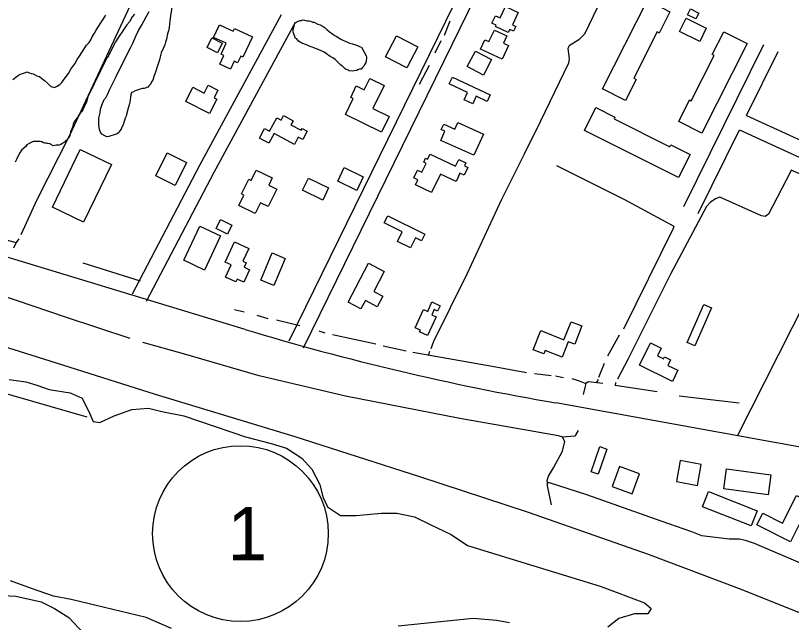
# Model space of a CAD drawing. Extents: x 3361039 to 3398939, y 576572 to 602007.
# Drawn here: x 3384364 to 3385821, y 582965 to 584104 of the extents above; entities that cross this region are included whole.
import ezdxf

# ---------------------------------------------------------------- set-up
doc = ezdxf.new("R2010")
doc.units = 0
for name, color, linetype in [('V-BLDG-OTLN', 7, 'Continuous'), ('V-RAIL-TRAK', 7, 'Continuous'), ('V-ROAD-CNTR', 7, 'Continuous'), ('V-ROAD-IDEN', 7, 'Continuous'), ('V-SITE-VEGE', 7, 'Continuous'), ('V-TOPO-SHOR', 7, 'Continuous')]:
    doc.layers.add(name, color=color, linetype=linetype)

msp = doc.modelspace()

# ---------------------------------------------------------------- linework, layer by layer
at = {"layer": 'V-BLDG-OTLN'}
for points in [[(3385466.3, 583966.4), (3385550.7, 584132.7), (3385592.8, 584111.3), (3385572.4, 584071.3), (3385568.6, 584073.2), (3385524.7, 583986.7), (3385529.4, 583984.3), (3385509.3, 583944.6)], [(3385289, 584072.2), (3385265, 584083.5), (3385266.2, 584085.9), (3385258.3, 584089.6), (3385265, 584103.8), (3385274, 584099.6), (3385284, 584120.9), (3385307.9, 584109.7), (3385296.9, 584086.5), (3385303.1, 584083.5), (3385299, 584074.6), (3385291.8, 584078)], [(3385641.2, 584097.8), (3385625.6, 584105.7), (3385631.2, 584116.6), (3385646.8, 584108.7)], [(3385648.8, 584055.6), (3385611, 584074.1), (3385623.3, 584099.2), (3385661.1, 584080.6)], [(3384746.7, 584086.7), (3384772.5, 584074.7), (3384775, 584080), (3384808.8, 584064.2), (3384791, 584026), (3384786.8, 584028), (3384780.8, 584015.3), (3384774.3, 584018.3), (3384767.3, 584003.3), (3384747.3, 584012.6), (3384755, 584029.2), (3384749.9, 584031.6), (3384759.4, 584052), (3384735.6, 584063.1)], [(3385119.2, 584045.3), (3385098.8, 584005.9), (3385058.9, 584026.6), (3385079.3, 584066)], [(3385277.5, 584021.9), (3385237.1, 584040.9), (3385245.3, 584058.6), (3385252.8, 584055.1), (3385263, 584076.9), (3385286.5, 584065.9), (3385280, 584052.1), (3385289.6, 584047.6)], [(3385737.9, 584051.4), (3385652.5, 583883.5), (3385609.3, 583905.5), (3385629.7, 583945.7), (3385632.4, 583944.3), (3385675.6, 584029.1), (3385672.2, 584030.8), (3385694, 584073.7)], [(3384732.5, 584062), (3384752.2, 584052.5), (3384743.4, 584034.4), (3384723.7, 584043.9)], [(3385242.5, 583992.3), (3385212, 584008.3), (3385227.4, 584037.5), (3385257.8, 584021.5)], [(3385050.8, 583885.4), (3384983.5, 583918.6), (3384998, 583948.1), (3384993.3, 583950.5), (3385003.8, 583971.9), (3385018.6, 583964.6), (3385029.1, 583986), (3385056.3, 583972.6), (3385035, 583929.5), (3385065.2, 583914.6)], [(3385184.2, 583988.4), (3385255.1, 583955.6), (3385249.3, 583943), (3385228.9, 583952.5), (3385222.4, 583938.5), (3385206.1, 583946.1), (3385212.5, 583959.8), (3385178.3, 583975.7)], [(3384727.9, 583920.1), (3384683.5, 583943), (3384697.1, 583969.4), (3384717.9, 583958.7), (3384725.5, 583973.4), (3384743.9, 583964), (3384736.6, 583949.9), (3384741.9, 583947.2)], [(3385608.8, 583799.9), (3385432.1, 583888.3), (3385453.7, 583931.4), (3385489.4, 583913.5), (3385487.8, 583910.4), (3385592.4, 583858), (3385594.2, 583861.7), (3385630.6, 583843.5)], [(3384887.5, 583862.1), (3384849.5, 583882.5), (3384839.8, 583864.5), (3384821.9, 583874.2), (3384831.5, 583892.1), (3384840.9, 583887.1), (3384854.4, 583912.2), (3384862.5, 583907.9), (3384867.1, 583916.5), (3384885, 583906.8), (3384880.8, 583899.1), (3384900.2, 583888.7), (3384902, 583892), (3384911.4, 583887), (3384903.1, 583871.5), (3384894.8, 583875.9)], [(3385224.5, 583841.8), (3385162.5, 583869.9), (3385170.3, 583887.1), (3385163.3, 583890.3), (3385167.9, 583900.3), (3385189, 583890.7), (3385194.7, 583903.1), (3385242.5, 583881.4)], [(3384433.3, 583744.5), (3384485.5, 583852.7), (3384544, 583824.5), (3384491.8, 583716.3)], [(3384627.5, 583803.2), (3384648.6, 583846.2), (3384685.1, 583828.3), (3384663.9, 583785.3)], [(3385142.2, 583844.2), (3385190.2, 583821.2), (3385196.3, 583834), (3385209.7, 583827.6), (3385207, 583822), (3385213.2, 583819.1), (3385206.3, 583804.7), (3385198.5, 583808.4), (3385191.1, 583792.8), (3385161.9, 583806.7), (3385145.2, 583771.8), (3385114.8, 583786.4), (3385119.4, 583796.1), (3385111.6, 583799.8), (3385118.5, 583814.2), (3385127, 583810.2), (3385134.9, 583826.6), (3385130.4, 583828.7), (3385134, 583836.3), (3385137.6, 583834.5)], [(3384981, 583818.7), (3385016.8, 583801.6), (3385004.6, 583776.1), (3384968.8, 583793.3)], [(3384854.5, 583778.6), (3384838.5, 583745.7), (3384823.8, 583752.8), (3384814, 583732.7), (3384783.4, 583747.6), (3384792.8, 583767), (3384788.2, 583769.3), (3384801.7, 583797), (3384806.3, 583794.8), (3384815.6, 583814), (3384845.8, 583799.3), (3384839.3, 583786)], [(3384914, 583798.7), (3384951.6, 583780.5), (3384940.7, 583757.9), (3384903, 583776.2)], [(3384761.9, 583694.1), (3384740.4, 583704.6), (3384748.6, 583721.2), (3384770.1, 583710.6)], [(3385062.7, 583728.3), (3385132.2, 583694), (3385126, 583681.5), (3385114.9, 583687), (3385105.6, 583668), (3385081.1, 583680.1), (3385090, 583698.2), (3385056.1, 583715)], [(3384748.9, 583690.6), (3384718.6, 583626.4), (3384679.6, 583644.9), (3384709.9, 583709)], [(3384792.5, 583603.6), (3384780, 583609.5), (3384777.6, 583604.2), (3384758.2, 583613.3), (3384768.9, 583636.2), (3384757.3, 583641.6), (3384775, 583679.6), (3384802.2, 583666.9), (3384791, 583642.9), (3384796.9, 583640.1), (3384793.1, 583632), (3384803.5, 583627.2)], [(3384824.2, 583607.7), (3384845.8, 583658.6), (3384870.4, 583648.2), (3384848.8, 583597.3)], [(3384988.2, 583566.3), (3385026.8, 583639.4), (3385056.3, 583623.8), (3385036.7, 583586.5), (3385053.4, 583577.7), (3385042.9, 583557.8), (3385020.8, 583569.5), (3385012.4, 583553.5)], [(3385114.3, 583518.4), (3385129.9, 583552.6), (3385137.8, 583549), (3385145.9, 583566.6), (3385161, 583559.7), (3385156.2, 583549.3), (3385149.8, 583552.3), (3385145.4, 583542.7), (3385153.5, 583539), (3385137.4, 583503.8), (3385122.5, 583510.5), (3385124.1, 583513.9)], [(3385624.9, 583490.6), (3385656.1, 583562.2), (3385670.9, 583555.7), (3385639.7, 583484.1)], [(3385350.1, 583513.1), (3385393.8, 583495.8), (3385407.2, 583529.6), (3385427.5, 583521.6), (3385413.9, 583487.3), (3385401.8, 583492.1), (3385390.4, 583463.2), (3385358.4, 583475.9), (3385355.7, 583469.1), (3385335.8, 583477)], [(3385597.3, 583417.6), (3385535.8, 583447.8), (3385556.3, 583489.7), (3385576.2, 583479.9), (3385569.3, 583465.8), (3385580.9, 583460.1), (3385582.6, 583463.6), (3385593.9, 583458.1), (3385588.7, 583447.6), (3385607.5, 583438.4)], [(3385474.4, 583290.5), (3385457.8, 583243.4), (3385444.6, 583248.1), (3385461.2, 583295.2)], [(3385651.4, 583261.8), (3385612.1, 583268.9), (3385604.9, 583229.6), (3385644.3, 583222.4)], [(3385535.3, 583243.9), (3385497.8, 583257.7), (3385484, 583220.2), (3385521.6, 583206.4)], [(3385777.5, 583205), (3385694.2, 583216.3), (3385699.2, 583253.4), (3385782.5, 583242.1)], [(3385745.2, 583146.4), (3385653.6, 583182.5), (3385664.9, 583210.9), (3385756.4, 583174.8)], [(3385856.1, 583190.5), (3385819, 583116.6), (3385756.2, 583148.2), (3385767.2, 583170.2), (3385804.4, 583151.5), (3385830.5, 583203.4)]]:
    msp.add_lwpolyline(points, close=True, dxfattribs=at)
at = {"layer": 'V-RAIL-TRAK'}
msp.add_lwpolyline([(3385897.1, 582959), (3385723.1, 583028.1), (3385552.3, 583092.7), (3385327, 583171.7), (3385123.3, 583238.4), (3384889.1, 583313.7), (3384627, 583392.9), (3384441, 583451.9), (3384235.3, 583516.2)], dxfattribs=at)
at = {"layer": 'V-ROAD-CNTR'}
for points in [[(3385719.9, 583315.7), (3386055, 583977.9), (3386329.1, 584522.2), (3386660, 585157.5)], [(3384878, 583493.6), (3385264.9, 584284.5), (3385582.1, 584917.9)], [(3384904.9, 583480.4), (3385291.8, 584271.2), (3385616.5, 584919.5)], [(3384583.5, 583582.2), (3384710.4, 583824.3), (3384863.2, 584105.8)], [(3384610.1, 583568.3), (3384736.9, 583810.2), (3384889.6, 584091.5)], [(3385618.9, 583745.7), (3385769.3, 584049.7)], [(3385736.7, 583916.3), (3385796.1, 584036.4)], [(3385736.7, 583916.3), (3385969.4, 583810.2)], [(3385645.8, 583732.4), (3385723.4, 583889.4)], [(3385723.4, 583889.4), (3385957, 583782.9)], [(3384794.9, 583515.1), (3384263, 583676.6)], [(3386141.8, 583241.2), (3385892.8, 583284.5), (3385378.7, 583377.2)]]:
    msp.add_lwpolyline(points, dxfattribs=at)
msp.add_arc((3386215.8, 588226), 4920.5, 253.2153, 260.2048, dxfattribs=at)
at = {"layer": 'V-ROAD-IDEN'}
msp.add_circle((3384786.2, 583132), 165, dxfattribs=at)
msp.add_circle((3384786.2, 583132), 165, dxfattribs=at)
at = {"layer": 'V-SITE-VEGE'}
for points in [[(3384658.4, 584127.1), (3384654.6, 584103.4), (3384653.8, 584094.1), (3384652.3, 584081.9), (3384650.8, 584075.4), (3384649.3, 584069.7), (3384647.1, 584059.7), (3384645.6, 584053.9), (3384644.2, 584048.9), (3384641.3, 584042.5), (3384637.6, 584033.9), (3384635.4, 584026.7), (3384633.9, 584021), (3384629.5, 584006), (3384627.3, 583999.5), (3384623.7, 583989.5), (3384621.5, 583983.1), (3384619.3, 583979.5), (3384617.8, 583975.9), (3384614.2, 583972.3), (3384612, 583969.5), (3384605.6, 583967.4), (3384602, 583967.4), (3384597.6, 583966), (3384588.3, 583962.5), (3384584, 583960.3), (3384581.8, 583959.6), (3384580.3, 583955.3), (3384578.8, 583941.7), (3384577.3, 583936.7), (3384575.1, 583930.3), (3384572.9, 583920.9), (3384571.5, 583915.2), (3384570, 583911.6), (3384568.5, 583907.3), (3384567.1, 583903.8), (3384566.3, 583900.2), (3384563.4, 583894.5), (3384562, 583890.9), (3384559.1, 583887.3), (3384557.6, 583884.4), (3384554.7, 583882.3), (3384551.1, 583880.9), (3384538.9, 583877.4), (3384535.3, 583876.7), (3384531.7, 583878.2), (3384526, 583881.8), (3384523.2, 583885.4), (3384521.8, 583890.4), (3384520.4, 583899.1), (3384520.5, 583911.3), (3384522.7, 583921.3), (3384523.5, 583928.5), (3384525.7, 583935.6), (3384530, 583946.4), (3384533.7, 583949.9), (3384536.6, 583955.7), (3384540.9, 583965.7), (3384547.5, 583978.5), (3384552.6, 583990), (3384573.7, 584031.5), (3384579.5, 584043.6), (3384583.9, 584052.2), (3384589.7, 584065.1), (3384594.8, 584075.8), (3384600.6, 584085.1), (3384609.4, 584101.6), (3384614.5, 584111.6)], [(3384358.8, 583984.2), (3384366.7, 583990.6), (3384372.5, 583994.1), (3384376.8, 583995.5), (3384382.5, 583996.9), (3384385.4, 583998.3), (3384388.3, 583996.9), (3384393.3, 583995.4), (3384396.9, 583994.7), (3384404, 583991), (3384409, 583989.6), (3384413.3, 583985.9), (3384418.3, 583982.3), (3384424, 583977.3), (3384430.4, 583970.7), (3384432.6, 583970), (3384436.9, 583969.3), (3384441.9, 583971.4), (3384447, 583974.9), (3384450.6, 583978.5), (3384453.5, 583982.1), (3384463.6, 583995.6), (3384468, 584003.5), (3384475.2, 584013.5), (3384479.6, 584021.4), (3384484, 584027.8), (3384497, 584048.5), (3384502.1, 584053.5), (3384505, 584058.5), (3384507.9, 584064.2), (3384512.3, 584070.7), (3384515.2, 584076.4), (3384518.1, 584081.4), (3384533.3, 584105)], [(3384587.2, 584106.7), (3384582.8, 584101.8), (3384577.7, 584092.5), (3384572.7, 584086.7), (3384563.9, 584073.2), (3384559.6, 584067.5), (3384556, 584061.7), (3384551.6, 584054.6)], [(3384551.6, 584054.6), (3384548.7, 584048.9), (3384545.1, 584042.4), (3384542.9, 584038.1), (3384541.4, 584034.6), (3384539.2, 584031), (3384537.8, 584026.7), (3384535.6, 584024.6), (3384499.9, 583951.6), (3384498.5, 583947.3), (3384497, 583941.6), (3384494.1, 583935.1), (3384491.9, 583931.6), (3384490.4, 583927.3), (3384487.5, 583923.7), (3384486.1, 583921.6), (3384483.9, 583918), (3384481.7, 583915.8), (3384481, 583913.7), (3384478.8, 583911.6), (3384475.2, 583906.6), (3384473, 583902.3), (3384472.3, 583900.1), (3384471.6, 583896.5), (3384469.4, 583891.5), (3384467.2, 583885.8), (3384466.4, 583881.5), (3384465, 583877.2), (3384463.5, 583874.3), (3384462.1, 583872.2), (3384460.6, 583870.8), (3384458.4, 583869.3), (3384455.6, 583866.5), (3384453.4, 583865.1), (3384451.9, 583863.7), (3384449.1, 583862.2), (3384445.5, 583860.8), (3384440.4, 583860.9), (3384436.8, 583860.2), (3384434.7, 583859.5), (3384430.4, 583862.4), (3384428.3, 583863.1), (3384424, 583863.8), (3384421.8, 583864.6), (3384418.9, 583864.6), (3384416.1, 583865.3), (3384413.2, 583866.8), (3384410.3, 583867.5), (3384396.7, 583867.6), (3384389.5, 583864.1), (3384385.2, 583861.2), (3384383, 583858.4), (3384379.4, 583855.5), (3384375.1, 583851.3), (3384372.1, 583846.3), (3384369.2, 583842), (3384365.6, 583834.1), (3384363.4, 583829.1)], [(3384352.2, 583421.2), (3384383.3, 583417.1), (3384404, 583410.8), (3384426.8, 583402.5), (3384466.2, 583396.3), (3384489, 583385.9), (3384503.6, 583356.9), (3384509.8, 583342.3), (3384522.2, 583340.3), (3384549.2, 583352.7), (3384582.4, 583365.2), (3384613.5, 583367.2), (3384638.4, 583361), (3384679.9, 583352.7), (3384796, 583313.3), (3384843.7, 583300.8), (3384872.7, 583292.5), (3384901.8, 583273.8), (3384920.4, 583253.1), (3384935, 583224), (3384941.2, 583201.2), (3384949.5, 583182.5), (3384974.4, 583165.9), (3385003.4, 583165.9), (3385051.1, 583170.1), (3385080.1, 583170.1), (3385113.3, 583163.8), (3385142.4, 583149.3), (3385181.8, 583130.6), (3385212.9, 583109.9), (3385461.8, 583033.1), (3385544.7, 583001.9), (3385557.2, 582991.5), (3385551, 582981.2), (3385526.1, 582981.2), (3385497, 582972.9)], [(3384657, 582954.2), (3384609.3, 582974.9), (3384468.3, 583008.2), (3384435.1, 583014.4), (3384393.6, 583028.9), (3384354.2, 583043.4)], [(3384292, 583018.5), (3384364.6, 583014.4), (3384412.3, 583004), (3384437.2, 582991.5), (3384464.1, 582974.9), (3384491.1, 582945.9), (3384503.6, 582925.1), (3384507.7, 582908.5), (3384503.6, 582891.9), (3384466.2, 582885.7), (3384441.3, 582885.7), (3384424.7, 582887.8), (3384410.2, 582887.8), (3384350.1, 582881.5)], [(3385291.7, 582964.6), (3385266.8, 582968.7), (3385223.3, 582972.9), (3385082.2, 582958.3)], [(3385497, 582972.9), (3385476.3, 582956.3)]]:
    msp.add_lwpolyline(points, dxfattribs=at)
msp.add_lwpolyline([(3385013.8, 584044.9), (3385022.3, 584028.3), (3385023, 584026.2), (3385023, 584024), (3385022.2, 584019), (3385021.5, 584016.1), (3385020, 584012.6), (3385017.9, 584009), (3385015.7, 584006.8), (3385012.8, 584003.3), (3385009.9, 584003.3), (3385007.8, 584002.6), (3385004.9, 584001.2), (3384999.8, 584000.5), (3384996.3, 583999.8), (3384990.5, 584000.6), (3384988.4, 584001.3), (3384984.8, 584002.8), (3384982.6, 584004.2), (3384977.7, 584009.3), (3384974.8, 584010.7), (3384964.1, 584021.6), (3384959.8, 584024.5), (3384954.8, 584027.4), (3384947.7, 584032.4), (3384943.4, 584035.3), (3384935.5, 584039), (3384930.5, 584041.2), (3384926.2, 584042.6), (3384919.1, 584045.6), (3384914, 584047), (3384910.5, 584049.2), (3384903.3, 584051.4), (3384898.3, 584054.3), (3384895.4, 584055.8), (3384891.9, 584060.1), (3384889.7, 584060.8), (3384886.2, 584069.5), (3384885.5, 584073.1), (3384885.5, 584078.1), (3384888.5, 584089.6), (3384890.7, 584091.7), (3384893.5, 584093.1), (3384897.9, 584094.5), (3384900.7, 584094.5), (3384903.6, 584095.9), (3384906.5, 584095.2), (3384910.8, 584094.4), (3384915.1, 584094.4), (3384918, 584093.7), (3384922.2, 584091.5), (3384924.4, 584091.5), (3384931.6, 584087.8), (3384935.8, 584086.4), (3384939.4, 584084.9), (3384945.1, 584081.3), (3384948.7, 584077.7), (3384953, 584074), (3384959.4, 584069), (3384963.7, 584066.8), (3384967.3, 584064.6), (3384973.7, 584060.3), (3384977.3, 584058.8), (3384983, 584055.9), (3384987.3, 584054.4), (3384990.9, 584052.2), (3384996.6, 584050.8), (3385005.9, 584047.8), (3385010.9, 584045.6)], close=True, dxfattribs=at)
at = {"layer": 'V-TOPO-SHOR'}
for p, q in [((3385169.4, 584067.3), (3385180.1, 584094.4)), ((3385151.8, 584033.9), (3385163.1, 584057.5)), ((3385122.7, 583975.5), (3385141.1, 584010.9)), ((3384370.3, 583685.4), (3384365.3, 583678.2)), ((3384598.6, 583605.4), (3384490.6, 583639.6)), ((3384775, 583552.4), (3384793.2, 583548.1)), ((3384816.8, 583541.6), (3384837.7, 583535.9)), ((3384853.8, 583533), (3384897.7, 583522.2)), ((3384933.2, 583512.2), (3384944.4, 583508.6)), ((3384959, 583505.7), (3385040.6, 583488.4)), ((3385497.7, 583504.1), (3385475.8, 583465.2)), ((3385054.5, 583484.1), (3385097.7, 583474.7)), ((3385141, 583474), (3385139.1, 583467.4)), ((3385469.4, 583451.3), (3385458.7, 583424.8)), ((3385338.2, 583432.5), (3385369.6, 583428.8)), ((3385378, 583428.1), (3385392.6, 583425.2)), ((3385458, 583421.3), (3385454, 583415)), ((3385490.8, 583415.5), (3385490.1, 583409.9)), ((3385568.9, 583398.2), (3385490.1, 583409.9)), ((3385723, 583376.9), (3385610, 583390.2))]:
    msp.add_line(p, q, dxfattribs=at)
for points in [[(3384646.6, 584961.7), (3384825.2, 584947.8), (3384994.8, 584940.4), (3384996.1, 584936.2), (3384990.5, 584924.4), (3384901.4, 584770), (3384803.1, 584582.2), (3384681.3, 584331.8), (3384578.6, 584121.7), (3384465.2, 583878.8), (3384403.6, 583758.5), (3384373.8, 583692.4)], [(3385489.1, 584188.2), (3385432.2, 584068.9), (3385421.8, 584058.6), (3385403.7, 584047), (3385400.9, 584042.2), (3385403.5, 584023.5), (3385402.1, 584014.5), (3385349.4, 583905.6), (3385319.3, 583844.2), (3385276.5, 583758.8), (3385211.2, 583618.8), (3385148.7, 583492.7), (3385143.8, 583478.9)], [(3385379.9, 583822.6), (3385507.2, 583758.8), (3385600.3, 583708.6), (3385598.9, 583704.5), (3385505.5, 583515.9)], [(3385855.8, 583798.3), (3385820.3, 583813.9), (3385818.9, 583811.1), (3385777.8, 583731.1), (3385771.5, 583727), (3385764.5, 583728.4), (3385686.6, 583763.2), (3385678.2, 583760.4), (3385668.4, 583753.5), (3385661.3, 583745.9), (3385594.1, 583618.6), (3385514.1, 583460), (3385494.3, 583421.8)], [(3384292.8, 583699.7), (3384333.9, 583686.1), (3384365.3, 583678.2), (3384360.3, 583667.8)], [(3384579, 583497.9), (3384457.8, 583537.9), (3384333.9, 583580.3), (3384282.3, 583595.6), (3384252.3, 583603.5)], [(3385370.5, 583185.9), (3385363.1, 583221.6), (3385362.7, 583227.1), (3385362.4, 583231.4), (3385364.6, 583239.7), (3385373.8, 583255.7), (3385390.7, 583287), (3385395.1, 583305.1), (3385390.9, 583312.8), (3385383.3, 583315.7), (3385198.5, 583347.7), (3384983.8, 583389.7), (3384821.4, 583427.8), (3384679.3, 583469.3), (3384602.7, 583490.8)], [(3385110.2, 583472.5), (3385258.8, 583446.4), (3385323.6, 583434)], [(3384498.5, 583350.2), (3384256.9, 583419.7), (3384244.4, 583417), (3384234.7, 583410.2), (3384230.5, 583404.6), (3384091.6, 583130.3), (3384051.7, 583039.1)], [(3385408.7, 583423), (3385422.6, 583418.7), (3385434.9, 583413.8)], [(3385467, 583413.6), (3385439.1, 583416.6), (3385434.9, 583413.8), (3385432.8, 583406.1), (3385429.9, 583392.9)], [(3385420.4, 583325.3), (3385414, 583314.8), (3385390.9, 583312.8)], [(3385846.5, 583073), (3385751.8, 583113.4), (3385734.4, 583119.1), (3385722.6, 583121.3), (3385703.7, 583121.5), (3385652.8, 583128.1), (3385634, 583135.2), (3385576.2, 583155.2), (3385436.9, 583205), (3385366.6, 583227.1), (3385362.7, 583227.1)]]:
    msp.add_lwpolyline(points, dxfattribs=at)

# ---------------------------------------------------------------- texts
at = {"layer": 'V-ROAD-IDEN'}
msp.add_text('1', height=100, rotation=0.1583, dxfattribs=at).set_placement((3384761.9, 583081.9))

doc.saveas('drawing.dxf')
